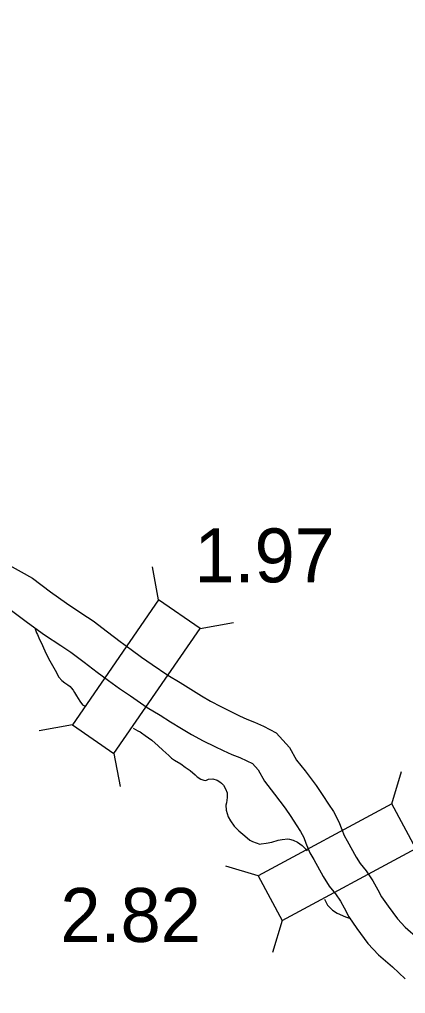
# Model space of a CAD drawing. Extents: x 0 to 3171, y 0 to 2059.
# Drawn here: x 467.8 to 528.3, y 1497.8 to 1650.4 of the extents above; entities that cross this region are included whole.
import ezdxf

# ---------------------------------------------------------------- set-up
doc = ezdxf.new("R2010")
doc.units = 0
for name, color, linetype in [('Default', 7, 'Continuous'), ('Level 10', 7, 'Continuous'), ('Level 20', 7, 'Continuous'), ('Level 58', 7, 'Continuous'), ('Level 8', 7, 'Continuous')]:
    doc.layers.add(name, color=color, linetype=linetype)

msp = doc.modelspace()

# ---------------------------------------------------------------- linework, layer by layer
at = {"layer": 'Default'}
msp.add_circle((410.95, 1647.45), 386.47, dxfattribs=at)
msp.add_circle((410.95, 1647.45), 386.47, dxfattribs=at)
at = {"layer": 'Level 10'}
for points in [[(466.19, 1564.96), (468.06, 1563.91), (469.88, 1562.89), (472.66, 1560.79), (475.16, 1558.98), (477.61, 1557.36), (479.34, 1556.21), (481.58, 1554.53), (483.59, 1552.98), (485.3, 1551.75), (486.95, 1550.55), (488.6, 1549.41), (491.03, 1547.73), (492.97, 1546.58), (494.66, 1545.53), (496.31, 1544.5), (497.72, 1543.66), (499.36, 1542.79), (501.01, 1541.96), (502.3, 1541.36), (503.42, 1540.83), (504.61, 1540.38), (506.04, 1539.73), (508.02, 1538.71), (510.13, 1536.41), (511.21, 1534.43), (512.54, 1532.71), (514.29, 1530.42), (515.35, 1528.87), (516.2, 1527.5), (516.97, 1526.34), (517.84, 1524.77), (518.28, 1523.54), (518.67, 1522.59), (519.15, 1521.78), (520.54, 1519.22), (521.18, 1518.2), (522.11, 1517.06), (523.18, 1515.49), (523.95, 1514.11), (524.53, 1513.01), (525.56, 1511.53), (527.01, 1509.53), (528.2, 1508.26), (530.24, 1506.48)], [(466.19, 1564.96), (468.06, 1563.91), (469.88, 1562.89), (472.66, 1560.79), (475.16, 1558.98), (477.61, 1557.36), (479.34, 1556.21), (481.58, 1554.53), (483.59, 1552.98), (485.3, 1551.75), (486.95, 1550.55), (488.6, 1549.41), (491.03, 1547.73), (492.97, 1546.58), (494.66, 1545.53), (496.31, 1544.5), (497.72, 1543.66), (499.36, 1542.79), (501.01, 1541.96), (502.3, 1541.36), (503.42, 1540.83), (504.61, 1540.38), (506.04, 1539.73), (508.02, 1538.71), (510.13, 1536.41), (511.21, 1534.43), (512.54, 1532.71), (514.29, 1530.42), (515.35, 1528.87), (516.2, 1527.5), (516.97, 1526.34), (517.84, 1524.77), (518.28, 1523.54), (518.67, 1522.59), (519.15, 1521.78), (520.54, 1519.22), (521.18, 1518.2), (522.11, 1517.06), (523.18, 1515.49), (523.95, 1514.11), (524.53, 1513.01), (525.56, 1511.53), (527.01, 1509.53), (528.2, 1508.26), (530.24, 1506.48)], [(466.59, 1557.86), (469.09, 1555.96), (471.74, 1554.05), (474.29, 1552.36), (475.87, 1551.3), (477.95, 1549.75), (480.01, 1548.17), (481.78, 1546.89), (483.48, 1545.65), (485.19, 1544.47), (487.8, 1542.67), (489.85, 1541.46), (491.48, 1540.43), (493.19, 1539.38), (494.77, 1538.43), (496.61, 1537.45), (498.39, 1536.56), (499.74, 1535.93), (501.06, 1535.3), (502.31, 1534.83), (503.43, 1534.32), (504.32, 1533.86), (505.22, 1532.89), (506.18, 1531.14), (507.78, 1529.06), (509.42, 1526.91), (510.33, 1525.58), (511.15, 1524.26), (511.83, 1523.23), (512.36, 1522.28), (512.68, 1521.38), (513.29, 1519.9), (513.93, 1518.82), (515.36, 1516.18), (516.31, 1514.68), (517.3, 1513.46), (518.07, 1512.34), (518.67, 1511.25), (519.4, 1509.87), (520.66, 1508.06), (522.37, 1505.71), (524.03, 1503.93), (526.22, 1502.03), (528.21, 1500.15)], [(466.59, 1557.86), (469.09, 1555.96), (471.74, 1554.05), (474.29, 1552.36), (475.87, 1551.3), (477.95, 1549.75), (480.01, 1548.17), (481.78, 1546.89), (483.48, 1545.65), (485.19, 1544.47), (487.8, 1542.67), (489.85, 1541.46), (491.48, 1540.43), (493.19, 1539.38), (494.77, 1538.43), (496.61, 1537.45), (498.39, 1536.56), (499.74, 1535.93), (501.06, 1535.3), (502.31, 1534.83), (503.43, 1534.32), (504.32, 1533.86), (505.22, 1532.89), (506.18, 1531.14), (507.78, 1529.06), (509.42, 1526.91), (510.33, 1525.58), (511.15, 1524.26), (511.83, 1523.23), (512.36, 1522.28), (512.68, 1521.38), (513.29, 1519.9), (513.93, 1518.82), (515.36, 1516.18), (516.31, 1514.68), (517.3, 1513.46), (518.07, 1512.34), (518.67, 1511.25), (519.4, 1509.87), (520.66, 1508.06), (522.37, 1505.71), (524.03, 1503.93), (526.22, 1502.03), (528.21, 1500.15)]]:
    msp.add_lwpolyline(points, dxfattribs=at)
at = {"layer": 'Level 20'}
for p, q in [((489.61, 1559.51), (488.66, 1564.7)), ((489.61, 1559.51), (488.66, 1564.7)), ((496.12, 1555.01), (501.32, 1555.96)), ((496.12, 1555.01), (501.32, 1555.96)), ((476.1, 1539.96), (470.91, 1539.01)), ((476.1, 1539.96), (470.91, 1539.01)), ((482.62, 1535.46), (483.57, 1530.26)), ((482.62, 1535.46), (483.57, 1530.26)), ((526.13, 1527.55), (527.65, 1532.61)), ((526.13, 1527.55), (527.65, 1532.61)), ((505.22, 1516.28), (500.16, 1517.79)), ((505.22, 1516.28), (500.16, 1517.79)), ((508.97, 1509.3), (507.46, 1504.25)), ((508.97, 1509.3), (507.46, 1504.25))]:
    msp.add_line(p, q, dxfattribs=at)
for points in [[(489.61, 1559.51), (476.1, 1539.96), (482.62, 1535.46), (496.12, 1555.01)], [(489.61, 1559.51), (476.1, 1539.96), (482.62, 1535.46), (496.12, 1555.01)], [(526.13, 1527.55), (505.22, 1516.28), (508.97, 1509.3), (529.89, 1520.58)], [(526.13, 1527.55), (505.22, 1516.28), (508.97, 1509.3), (529.89, 1520.58)]]:
    msp.add_lwpolyline(points, close=True, dxfattribs=at)
at = {"layer": 'Level 8'}
for points in [[(470.25, 1555.14), (470.46, 1554.37), (470.64, 1554.07), (470.84, 1553.57), (471.4, 1552.39), (471.94, 1551.19), (472.59, 1549.95), (473.39, 1548.51), (473.99, 1547.43), (474.45, 1546.89), (474.93, 1546.51), (475.37, 1546.23), (475.75, 1545.95), (475.91, 1545.71), (476.21, 1545.39), (476.45, 1545.03), (476.75, 1544.49), (477.25, 1543.63), (477.71, 1543.09), (477.89, 1542.97), (478.21, 1542.84)], [(470.25, 1555.14), (470.46, 1554.37), (470.64, 1554.07), (470.84, 1553.57), (471.4, 1552.39), (471.94, 1551.19), (472.59, 1549.95), (473.39, 1548.51), (473.99, 1547.43), (474.45, 1546.89), (474.93, 1546.51), (475.37, 1546.23), (475.75, 1545.95), (475.91, 1545.71), (476.21, 1545.39), (476.45, 1545.03), (476.75, 1544.49), (477.25, 1543.63), (477.71, 1543.09), (477.89, 1542.97), (478.21, 1542.84)], [(485.63, 1539.4), (486.36, 1539.01), (486.72, 1538.83), (486.92, 1538.69), (487.51, 1538.29), (488.57, 1537.53), (489.53, 1536.65), (490.27, 1535.99), (491.23, 1535.15), (491.65, 1534.71), (492.07, 1534.43), (493.07, 1533.81), (493.75, 1533.33), (494.55, 1532.77), (495.33, 1532.11), (495.67, 1531.79), (496.23, 1531.45), (496.69, 1531.25), (496.99, 1531.23), (497.43, 1531.45), (498.08, 1531.47), (498.76, 1531.25), (499.22, 1531.02), (499.48, 1530.8), (499.76, 1530.48), (500.1, 1529.93), (500.34, 1529.27), (500.34, 1528.53), (500.25, 1527.73), (500.15, 1527.37), (500.19, 1526.55), (500.51, 1525.53), (500.87, 1524.91), (501.45, 1524.07), (502.19, 1523.35), (503.09, 1522.53), (503.91, 1521.85), (504.31, 1521.65), (505.45, 1521.25), (505.67, 1521.29), (506.47, 1521.41), (507.32, 1521.55), (508.32, 1521.85), (508.98, 1522), (509.86, 1522.08), (510.12, 1522.02), (510.67, 1521.86), (511.35, 1521.58), (512.11, 1521.06), (512.65, 1520.46), (512.89, 1520.18)], [(485.63, 1539.4), (486.36, 1539.01), (486.72, 1538.83), (486.92, 1538.69), (487.51, 1538.29), (488.57, 1537.53), (489.53, 1536.65), (490.27, 1535.99), (491.23, 1535.15), (491.65, 1534.71), (492.07, 1534.43), (493.07, 1533.81), (493.75, 1533.33), (494.55, 1532.77), (495.33, 1532.11), (495.67, 1531.79), (496.23, 1531.45), (496.69, 1531.25), (496.99, 1531.23), (497.43, 1531.45), (498.08, 1531.47), (498.76, 1531.25), (499.22, 1531.02), (499.48, 1530.8), (499.76, 1530.48), (500.1, 1529.93), (500.34, 1529.27), (500.34, 1528.53), (500.25, 1527.73), (500.15, 1527.37), (500.19, 1526.55), (500.51, 1525.53), (500.87, 1524.91), (501.45, 1524.07), (502.19, 1523.35), (503.09, 1522.53), (503.91, 1521.85), (504.31, 1521.65), (505.45, 1521.25), (505.67, 1521.29), (506.47, 1521.41), (507.32, 1521.55), (508.32, 1521.85), (508.98, 1522), (509.86, 1522.08), (510.12, 1522.02), (510.67, 1521.86), (511.35, 1521.58), (512.11, 1521.06), (512.65, 1520.46), (512.89, 1520.18)], [(515.56, 1512.62), (516.08, 1511.67), (516.82, 1510.93), (517.56, 1510.45), (518.9, 1509.87), (519.65, 1509.59)], [(515.56, 1512.62), (516.08, 1511.67), (516.82, 1510.93), (517.56, 1510.45), (518.9, 1509.87), (519.65, 1509.59)]]:
    msp.add_lwpolyline(points, dxfattribs=at)

# ---------------------------------------------------------------- texts
at = {"layer": 'Level 58'}
for s, p in [('1.97', (495.21, 1562.26)), ('1.97', (495.21, 1562.26)), ('2.82', (474.23, 1505.93)), ('2.82', (474.23, 1505.93))]:
    msp.add_text(s, height=8.448, dxfattribs=at).set_placement(p)

doc.saveas('drawing.dxf')
